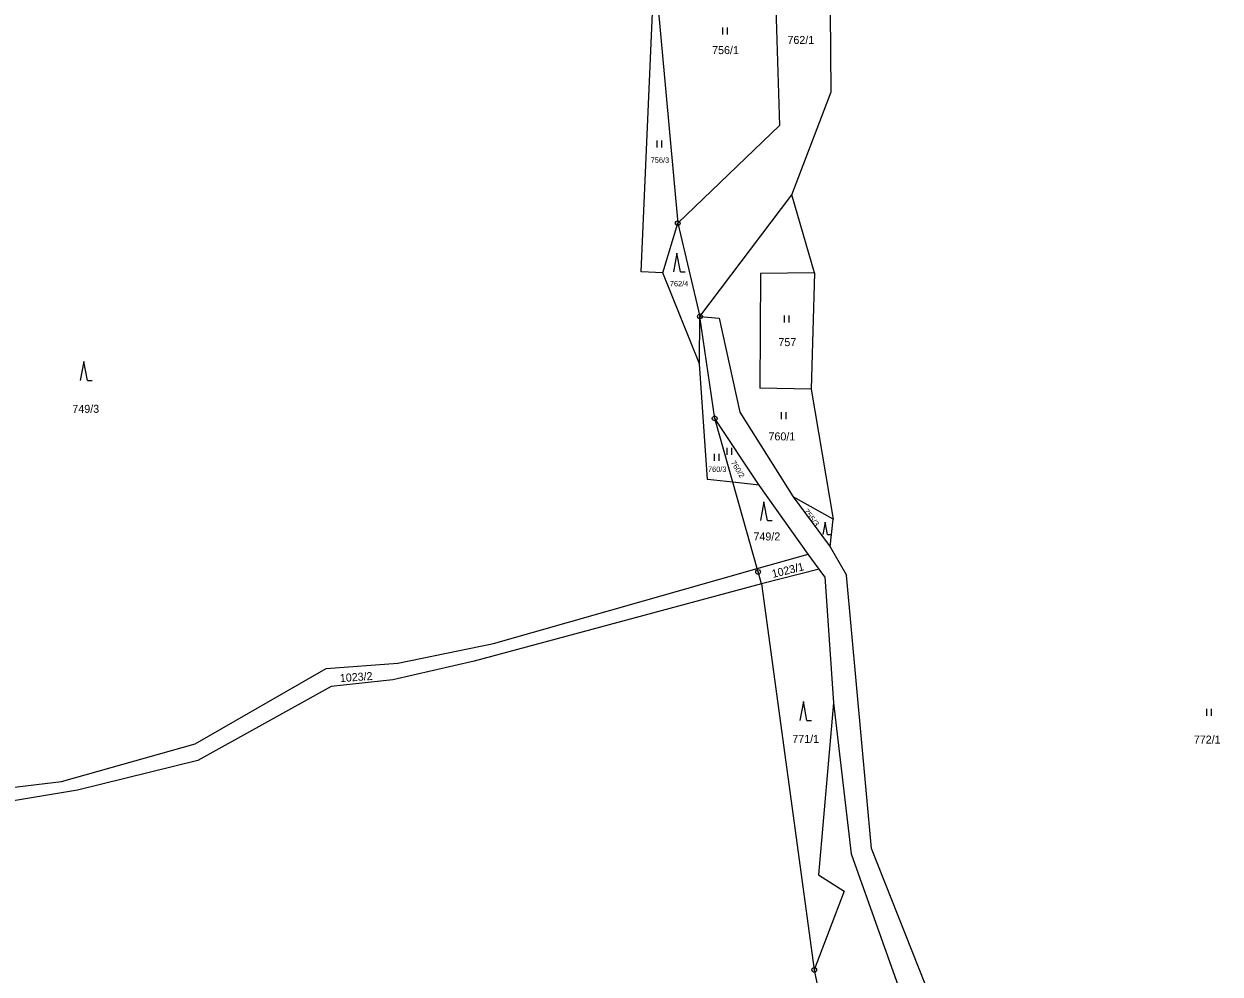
# Model space of a CAD drawing. Extents: x -754970 to -752637, y -970569 to -968179.
# Drawn here: x -754392.6 to -754138.4, y -970155.3 to -969953.5 of the extents above; entities that cross this region are included whole.
import ezdxf
from ezdxf.enums import TextEntityAlignment as Align

# ---------------------------------------------------------------- set-up
doc = ezdxf.new("R2010")
doc.units = 0
doc.header["$LTSCALE"] = 0.68
for name, color, linetype, lineweight in [('1', 7, 'Continuous', 25), ('3', 7, 'Continuous', 25), ('8', 7, 'Continuous', 25)]:
    doc.layers.add(name, color=color, linetype=linetype, lineweight=lineweight)
doc.layers.add('2', color=7, linetype='Continuous')

msp = doc.modelspace()

# ---------------------------------------------------------------- linework, layer by layer
at = {"layer": '1'}
for p, q in [((-754233.6, -969922.51), (-754232.03, -969975.11)), ((-754261.38, -970006.14), (-754258.61, -969941.38)), ((-754258.61, -969941.38), (-754253.64, -969995.86)), ((-754221.04, -969967.97), (-754221.2, -969951.01)), ((-754229.43, -969989.8), (-754221.04, -969967.97)), ((-754232.03, -969975.11), (-754253.64, -969995.86)), ((-754248.93, -970015.62), (-754229.43, -969989.8)), ((-754224.56, -970006.37), (-754229.43, -969989.8)), ((-754256.82, -970006.37), (-754253.64, -969995.86)), ((-754253.64, -969995.86), (-754248.93, -970015.62)), ((-754256.82, -970006.37), (-754261.38, -970006.14)), ((-754249.05, -970025.69), (-754256.82, -970006.37)), ((-754236.02, -970006.53), (-754236.18, -970030.87)), ((-754224.56, -970006.37), (-754236.02, -970006.53)), ((-754224.56, -970006.37), (-754225.27, -970031.1)), ((-754249.05, -970025.69), (-754248.93, -970015.62)), ((-754245.79, -970037.3), (-754248.93, -970015.62)), ((-754248.93, -970015.62), (-754244.81, -970016.04)), ((-754244.81, -970016.04), (-754240.45, -970035.94)), ((-754247.33, -970050.26), (-754249.05, -970025.69)), ((-754225.27, -970031.1), (-754236.18, -970030.87)), ((-754225.27, -970031.1), (-754220.64, -970058.73)), ((-754240.45, -970035.94), (-754229.11, -970053.92)), ((-754236.32, -970051.45), (-754245.79, -970037.3)), ((-754241.96, -970050.84), (-754245.79, -970037.3)), ((-754241.96, -970050.84), (-754247.33, -970050.26)), ((-754236.77, -970069.18), (-754241.96, -970050.84)), ((-754236.32, -970051.45), (-754241.96, -970050.84)), ((-754225.89, -970066.1), (-754236.32, -970051.45)), ((-754229.11, -970053.92), (-754221.22, -970064.57)), ((-754220.64, -970058.73), (-754229.11, -970053.92)), ((-754221.22, -970064.57), (-754220.64, -970058.73)), ((-754236.77, -970069.18), (-754225.89, -970066.1)), ((-754223.58, -970069.31), (-754225.89, -970066.1)), ((-754221.22, -970064.57), (-754217.77, -970070.6)), ((-754292.82, -970085.07), (-754236.77, -970069.18)), ((-754236.56, -970069.91), (-754236.77, -970069.18)), ((-754235.82, -970072.45), (-754236.56, -970069.91)), ((-754223.58, -970069.31), (-754235.82, -970072.45)), ((-754222.41, -970070.94), (-754223.58, -970069.31)), ((-754222.41, -970070.94), (-754220.57, -970097.68)), ((-754212.44, -970128.61), (-754217.77, -970070.6)), ((-754235.82, -970072.45), (-754296.93, -970088.85)), ((-754235.82, -970072.45), (-754224.62, -970154.43)), ((-754313.14, -970089.27), (-754292.82, -970085.07)), ((-754328.36, -970090.42), (-754313.14, -970089.27)), ((-754296.93, -970088.85), (-754314.21, -970092.81)), ((-754356.18, -970106.4), (-754328.36, -970090.42)), ((-754327.29, -970094.21), (-754355.61, -970109.93)), ((-754314.21, -970092.81), (-754327.29, -970094.21)), ((-754220.57, -970097.68), (-754223.7, -970134.26)), ((-754220.57, -970097.68), (-754216.79, -970129.79)), ((-754384.57, -970114.38), (-754356.18, -970106.4)), ((-754355.61, -970109.93), (-754381.2, -970116.27)), ((-754395.77, -970115.78), (-754384.57, -970114.38)), ((-754381.2, -970116.27), (-754429.26, -970124.26)), ((-754216.79, -970129.79), (-754195.3, -970189.96)), ((-754188.66, -970188.7), (-754212.44, -970128.61)), ((-754223.7, -970134.26), (-754218.25, -970137.73)), ((-754218.25, -970137.73), (-754224.62, -970154.43)), ((-754224.62, -970154.43), (-754215.47, -970199.68))]:
    msp.add_line(p, q, dxfattribs=at)
at = {"layer": '3'}
for p, q in [((-754244.061, -969955.78), (-754244.061, -969954.28)), ((-754243.06, -969955.78), (-754243.06, -969954.28)), ((-754258.041, -969979.75), (-754258.041, -969978.25)), ((-754257.04, -969979.75), (-754257.04, -969978.25)), ((-754253.05, -970006.17), (-754252.054, -970006.17)), ((-754230.951, -970016.93), (-754230.951, -970015.43)), ((-754229.95, -970016.93), (-754229.95, -970015.43)), ((-754379.09, -970029.23), (-754378.094, -970029.23)), ((-754231.571, -970037.45), (-754231.571, -970035.95)), ((-754230.57, -970037.45), (-754230.57, -970035.95)), ((-754243.111, -970045.03), (-754243.111, -970043.53)), ((-754242.11, -970045.03), (-754242.11, -970043.53)), ((-754245.851, -970046.32), (-754245.851, -970044.82)), ((-754244.85, -970046.32), (-754244.85, -970044.82)), ((-754234.58, -970059.01), (-754233.584, -970059.01)), ((-754221.798, -970061.98), (-754221.13, -970061.98)), ((-754141.231, -970100.48), (-754141.231, -970098.98)), ((-754140.23, -970100.48), (-754140.23, -970098.98)), ((-754226.2, -970101.44), (-754225.204, -970101.44))]:
    msp.add_line(p, q, dxfattribs=at)
for points in [[(-754253.05, -970006.17), (-754253.8, -970002.17), (-754254.55, -970006.17)], [(-754379.09, -970029.23), (-754379.84, -970025.23), (-754380.59, -970029.23)], [(-754234.58, -970059.01), (-754235.33, -970055.01), (-754236.08, -970059.01)], [(-754221.798, -970061.98), (-754222.3, -970059.3), (-754222.802, -970061.98)], [(-754226.2, -970101.44), (-754226.95, -970097.44), (-754227.7, -970101.44)]]:
    msp.add_lwpolyline(points, dxfattribs=at)
at = {"layer": '8'}
for centre, radius in [((-754253.64, -969995.8599), 0.5), ((-754253.64, -969995.8599), 0.0303), ((-754248.93, -970015.6199), 0.5), ((-754248.93, -970015.6199), 0.0303), ((-754245.79, -970037.2999), 0.5), ((-754245.79, -970037.2999), 0.0303), ((-754236.56, -970069.9099), 0.5), ((-754236.56, -970069.9099), 0.0303), ((-754224.62, -970154.4299), 0.5), ((-754224.62, -970154.4299), 0.0303)]:
    msp.add_circle(centre, radius, dxfattribs=at)

# ---------------------------------------------------------------- texts
at = {"layer": '2'}
for s, height, p in [('762/1', 1.7, (-754227.48, -969957.765)), ('756/1', 1.7, (-754243.49, -969959.925)), ('756/3', 1.14, (-754257.429, -969983.015)), ('762/4', 1.14, (-754253.349, -970009.245)), ('757', 1.7, (-754230.349, -970021.945)), ('749/3', 1.7, (-754379.43, -970036.115)), ('760/1', 1.7, (-754231.51, -970041.965)), ('760/3', 1.14, (-754245.249, -970048.665)), ('749/2', 1.7, (-754234.7, -970063.215)), ('771/1', 1.7, (-754226.45, -970106.205)), ('772/1', 1.7, (-754141.13, -970106.355))]:
    msp.add_text(s, height=height, dxfattribs=at).set_placement(p, align=Align.CENTER)
for s, rotation, width, p in [('760/2', 302, 1.05, (-754241.3749, -970048.3749)), ('755/3', 307, 1.1, (-754225.6759, -970058.6855))]:
    msp.add_text(s, height=1.14, rotation=rotation, dxfattribs=dict(at, width=width)).set_placement(p, align=Align.CENTER)
for s, rotation, p in [('1023/1', 14, (-754230.0421, -970070.3454)), ('1023/2', 4, (-754321.9098, -970093.0711))]:
    msp.add_text(s, height=1.7, rotation=rotation, dxfattribs=at).set_placement(p, align=Align.CENTER)

doc.saveas('drawing.dxf')
